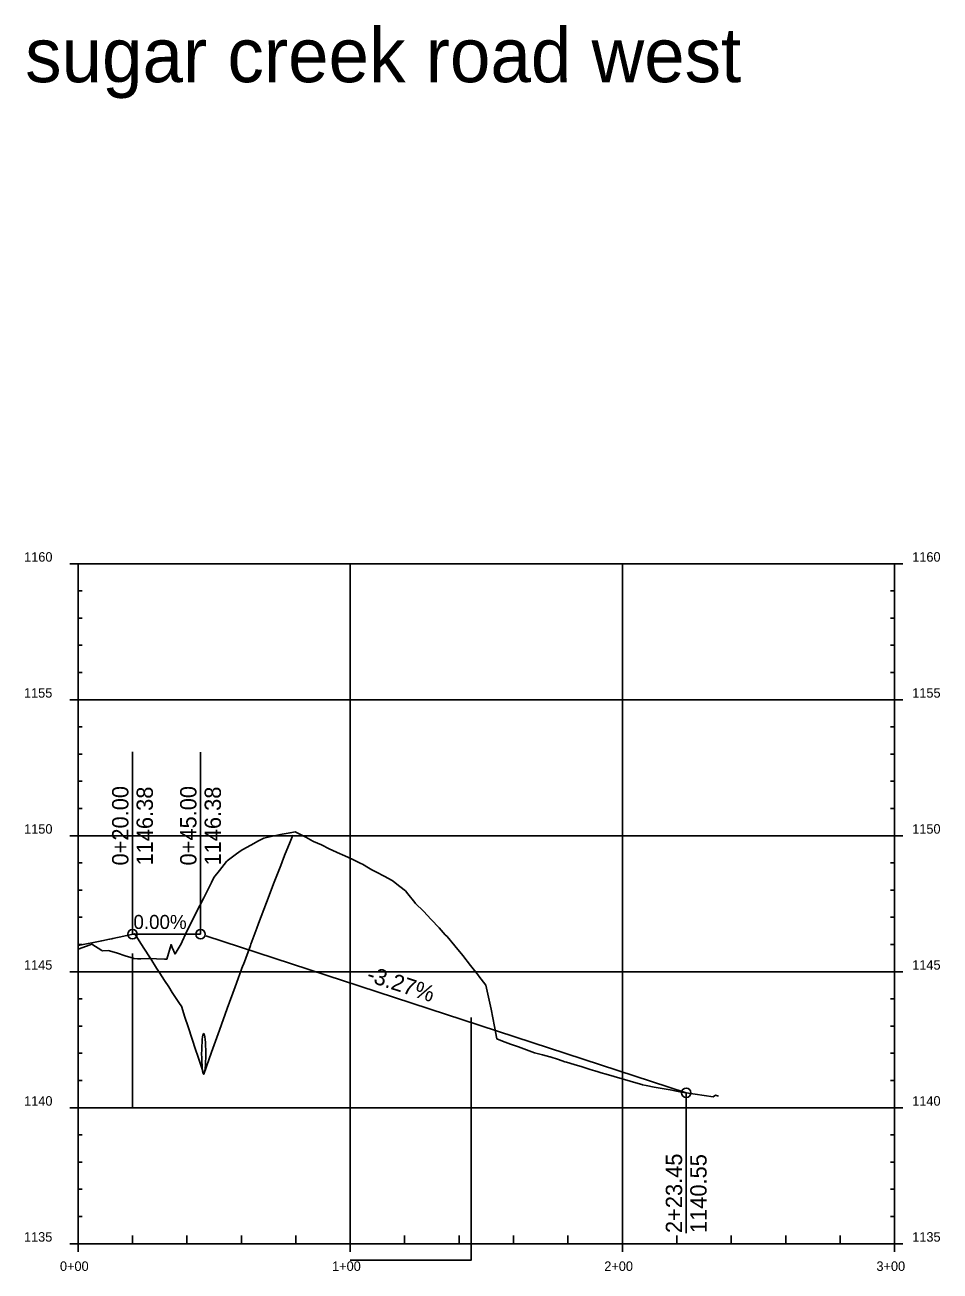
# Model space of a CAD drawing. Extents: x 688474 to 694748, y 765018 to 767373.
# Drawn here: x 694411.9 to 694748.1, y 765808.2 to 766266.3 of the extents above; entities that cross this region are included whole.
import ezdxf

# ---------------------------------------------------------------- set-up
doc = ezdxf.new("R2010")
doc.units = 0
for name, color, linetype in [('30', 7, 'Continuous'), ('37', 7, 'Continuous'), ('R_Drainage', 7, 'Continuous'), ('R_Exist Surface', 7, 'Continuous'), ('R_Fin Surface', 7, 'Continuous'), ('R_No Plot', 7, 'Continuous'), ('R_Vert Alg', 7, 'Continuous'), ('R_Vert Alg Annot', 7, 'Continuous')]:
    doc.layers.add(name, color=color, linetype=linetype)

msp = doc.modelspace()

# ---------------------------------------------------------------- linework, layer by layer
at = {"layer": '37'}
for p, q in [((694428.38, 766068.21), (694431.38, 766068.21)), ((694428.38, 766068.21), (694431.38, 766068.21)), ((694431.38, 765818.21), (694431.38, 766068.21)), ((694431.38, 766068.21), (694731.38, 766068.21)), ((694431.38, 766068.21), (694731.38, 766068.21)), ((694531.38, 765818.21), (694531.38, 766068.21)), ((694631.38, 765818.21), (694631.38, 766068.21)), ((694731.38, 765818.21), (694731.38, 766068.21)), ((694734.38, 766068.21), (694731.38, 766068.21)), ((694734.38, 766068.21), (694731.38, 766068.21)), ((694431.38, 766058.21), (694432.88, 766058.21)), ((694731.38, 766058.21), (694729.88, 766058.21)), ((694431.38, 766048.21), (694432.88, 766048.21)), ((694731.38, 766048.21), (694729.88, 766048.21)), ((694431.38, 766038.21), (694432.88, 766038.21)), ((694731.38, 766038.21), (694729.88, 766038.21)), ((694431.38, 766028.21), (694432.88, 766028.21)), ((694731.38, 766028.21), (694729.88, 766028.21)), ((694428.38, 766018.21), (694431.38, 766018.21)), ((694431.38, 766018.21), (694731.38, 766018.21)), ((694734.38, 766018.21), (694731.38, 766018.21)), ((694431.38, 766008.21), (694432.88, 766008.21)), ((694731.38, 766008.21), (694729.88, 766008.21)), ((694431.38, 765998.21), (694432.88, 765998.21)), ((694731.38, 765998.21), (694729.88, 765998.21)), ((694431.38, 765988.21), (694432.88, 765988.21)), ((694731.38, 765988.21), (694729.88, 765988.21)), ((694431.38, 765978.21), (694432.88, 765978.21)), ((694731.38, 765978.21), (694729.88, 765978.21)), ((694428.38, 765968.21), (694431.38, 765968.21)), ((694431.38, 765968.21), (694731.38, 765968.21)), ((694734.38, 765968.21), (694731.38, 765968.21)), ((694431.38, 765958.21), (694432.88, 765958.21)), ((694731.38, 765958.21), (694729.88, 765958.21)), ((694431.38, 765948.21), (694432.88, 765948.21)), ((694731.38, 765948.21), (694729.88, 765948.21)), ((694431.38, 765938.21), (694432.88, 765938.21)), ((694731.38, 765938.21), (694729.88, 765938.21)), ((694431.38, 765928.21), (694432.88, 765928.21)), ((694731.38, 765928.21), (694729.88, 765928.21)), ((694428.38, 765918.21), (694431.38, 765918.21)), ((694431.38, 765918.21), (694731.38, 765918.21)), ((694734.38, 765918.21), (694731.38, 765918.21)), ((694431.38, 765908.21), (694432.88, 765908.21)), ((694731.38, 765908.21), (694729.88, 765908.21)), ((694431.38, 765898.21), (694432.88, 765898.21)), ((694731.38, 765898.21), (694729.88, 765898.21)), ((694431.38, 765888.21), (694432.88, 765888.21)), ((694731.38, 765888.21), (694729.88, 765888.21)), ((694431.38, 765878.21), (694432.88, 765878.21)), ((694731.38, 765878.21), (694729.88, 765878.21)), ((694428.38, 765868.21), (694431.38, 765868.21)), ((694431.38, 765868.21), (694731.38, 765868.21)), ((694734.38, 765868.21), (694731.38, 765868.21)), ((694431.38, 765858.21), (694432.88, 765858.21)), ((694731.38, 765858.21), (694729.88, 765858.21)), ((694431.38, 765848.21), (694432.88, 765848.21)), ((694731.38, 765848.21), (694729.88, 765848.21)), ((694431.38, 765838.21), (694432.88, 765838.21)), ((694731.38, 765838.21), (694729.88, 765838.21)), ((694431.38, 765828.21), (694432.88, 765828.21)), ((694731.38, 765828.21), (694729.88, 765828.21)), ((694428.38, 765818.21), (694431.38, 765818.21)), ((694431.38, 765818.21), (694731.38, 765818.21)), ((694431.38, 765815.21), (694431.38, 765818.21)), ((694451.38, 765818.21), (694451.38, 765821.21)), ((694471.38, 765818.21), (694471.38, 765821.21)), ((694491.38, 765818.21), (694491.38, 765821.21)), ((694511.38, 765818.21), (694511.38, 765821.21)), ((694531.38, 765815.21), (694531.38, 765818.21)), ((694551.38, 765818.21), (694551.38, 765821.21)), ((694571.38, 765818.21), (694571.38, 765821.21)), ((694591.38, 765818.21), (694591.38, 765821.21)), ((694611.38, 765818.21), (694611.38, 765821.21)), ((694631.38, 765815.21), (694631.38, 765818.21)), ((694651.38, 765818.21), (694651.38, 765821.21)), ((694671.38, 765818.21), (694671.38, 765821.21)), ((694691.38, 765818.21), (694691.38, 765821.21)), ((694711.38, 765818.21), (694711.38, 765821.21)), ((694734.38, 765818.21), (694731.38, 765818.21)), ((694731.38, 765815.21), (694731.38, 765818.21))]:
    msp.add_line(p, q, dxfattribs=at)
at = {"layer": 'R_Drainage'}
msp.add_ellipse((694477.55, 765888.03), major_axis=(0, 7.5), ratio=0.1, dxfattribs=at)
at = {"layer": 'R_Exist Surface'}
msp.add_lwpolyline([(694431.38, 765926.45), (694435.79, 765928.13), (694436.41, 765928.39), (694440.06, 765925.99), (694440.1, 765925.96), (694440.31, 765925.81), (694440.49, 765925.84), (694442.41, 765926.06), (694442.94, 765925.89), (694445.83, 765925), (694448.71, 765924.1), (694451.59, 765923.21), (694451.92, 765923.11), (694453.19, 765922.95), (694454.48, 765922.98), (694457.26, 765923.05), (694457.36, 765923.05), (694460.24, 765922.96), (694463.13, 765922.89), (694464.05, 765922.86), (694465.58, 765928.19), (694466.01, 765927.16), (694467.06, 765924.72), (694467.07, 765924.73), (694468.9, 765927.82), (694468.98, 765927.96), (694471.57, 765933.61), (694471.78, 765934.04), (694474.66, 765939.75), (694477.55, 765945.43), (694480.43, 765951.07), (694481.33, 765952.81), (694483.32, 765955.41), (694485.87, 765958.72), (694486.2, 765958.98), (694489.08, 765961.2), (694490.91, 765962.59), (694491.97, 765963.18), (694494.85, 765964.77), (694497.74, 765966.33), (694499.63, 765967.32), (694500.62, 765967.55), (694503.5, 765968.18), (694506.39, 765968.76), (694509.27, 765969.31), (694511.21, 765969.65), (694512.16, 765969.18), (694515.04, 765967.67), (694517.62, 765966.24), (694517.92, 765966.12), (694520.81, 765964.82), (694523.69, 765963.45), (694526.32, 765962.14), (694526.58, 765962.03), (694529.46, 765960.77), (694532.34, 765959.44), (694535.23, 765958.04), (694535.88, 765957.7), (694538.11, 765956.42), (694539.35, 765955.68), (694541, 765954.84), (694543.88, 765953.3), (694546.76, 765951.69), (694547.28, 765951.39), (694549.65, 765949.54), (694551.65, 765947.91), (694552.53, 765946.85), (694555.12, 765943.63), (694555.42, 765943.35), (694558.3, 765940.46), (694561.18, 765937.46), (694564.07, 765934.35), (694566.33, 765931.82), (694566.95, 765931.11), (694569.83, 765927.69), (694572.72, 765924.16), (694575.6, 765920.52), (694576.59, 765919.24), (694578.49, 765916.81), (694578.63, 765916.63), (694581.2, 765913.24), (694581.42, 765912.21), (694583.13, 765904.4), (694584.36, 765898.02), (694585.27, 765893.48), (694587.3, 765892.72), (694590.23, 765891.63), (694590.63, 765891.48), (694593.17, 765890.54), (694596.1, 765889.46), (694599.04, 765888.38), (694599.08, 765888.37), (694601.98, 765887.64), (694604.76, 765886.94), (694604.91, 765886.89), (694607.85, 765885.92), (694610.19, 765885.14), (694610.79, 765884.96), (694613.72, 765884.07), (694616.66, 765883.19), (694619.6, 765882.3), (694621.21, 765881.82), (694622.53, 765881.39), (694623.58, 765881.06), (694625.47, 765880.5), (694628.4, 765879.64), (694631.34, 765878.78), (694634.28, 765877.92), (694637.21, 765877.07), (694638.53, 765876.69), (694638.72, 765876.62), (694638.75, 765876.61), (694640.15, 765876.33), (694643.09, 765875.76), (694646.02, 765875.23), (694648.96, 765874.73), (694651.29, 765874.36), (694651.89, 765874.22), (694653.08, 765873.94), (694654.83, 765873.67), (694664.75, 765872.23), (694665.58, 765872.84), (694666.7, 765872.52)], dxfattribs=at)
at = {"layer": 'R_Fin Surface'}
msp.add_lwpolyline([(694431.38, 765927.8), (694431.41, 765927.8), (694440.06, 765929.57), (694442.94, 765930.15), (694443.81, 765930.33), (694444.22, 765930.41), (694445.83, 765930.76), (694445.9, 765930.78), (694447.08, 765931.03), (694448.71, 765931.4), (694451.59, 765932.03), (694452.19, 765932.17), (694454.48, 765928.56), (694457.36, 765924.03), (694458.08, 765922.91), (694460.24, 765919.52), (694461.39, 765917.74), (694463.13, 765915.03), (694464.69, 765912.63), (694466.01, 765910.57), (694468.9, 765906.14), (694469.33, 765905.49), (694470.64, 765901.47), (694471.78, 765897.99), (694474.66, 765889.24), (694474.91, 765888.49), (694474.94, 765888.41), (694475, 765888.22), (694476.71, 765883.07), (694477.55, 765880.54), (694477.55, 765880.53), (694480.43, 765888.67), (694483.32, 765896.75), (694486.2, 765904.75), (694489.08, 765912.68), (694491.97, 765920.52), (694492.12, 765920.91), (694494.7, 765927.89), (694494.85, 765928.3), (694497.09, 765934.27), (694497.74, 765936), (694500.62, 765943.63), (694503.5, 765951.17), (694505.85, 765957.23), (694506.39, 765958.63), (694507.29, 765960.94), (694509.27, 765966.01), (694510.24, 765968.47)], dxfattribs=at)
at = {"layer": 'R_No Plot'}
msp.add_line((694451.38, 765868.21), (694451.38, 765924.93), dxfattribs=at)
msp.add_lwpolyline([(694531.38, 765812.21), (694575.83, 765812.21), (694575.83, 765901.33)], dxfattribs=at)
at = {"layer": 'R_Vert Alg'}
for p, q in [((694451.38, 765932.01), (694476.38, 765932.01)), ((694478.36, 765931.36), (694654.83, 765873.71))]:
    msp.add_line(p, q, dxfattribs=at)
for centre in [(694451.38, 765932.01), (694476.38, 765932.01), (694654.83, 765873.71)]:
    msp.add_circle(centre, 1.75, dxfattribs=at)
at = {"layer": 'R_Vert Alg Annot'}
for p, q in [((694451.38, 765932.01), (694451.38, 765999.03)), ((694476.38, 765932.01), (694476.38, 765998.93)), ((694654.83, 765873.71), (694654.83, 765822.14))]:
    msp.add_line(p, q, dxfattribs=at)

# ---------------------------------------------------------------- texts
at = {"layer": '30'}
for s, p in [('1160', (694411.57, 766068.96)), ('1160', (694411.57, 766068.96)), ('1160', (694737.88, 766068.96)), ('1160', (694737.88, 766068.96)), ('1155', (694411.51, 766018.96)), ('1155', (694737.88, 766018.96)), ('1150', (694411.57, 765968.96)), ('1150', (694737.88, 765968.96)), ('1145', (694411.51, 765918.96)), ('1145', (694737.88, 765918.96)), ('1140', (694411.57, 765868.96)), ('1140', (694737.88, 765868.96)), ('1135', (694411.51, 765818.96)), ('1135', (694737.88, 765818.96)), ('0+00', (694424.73, 765808.21)), ('1+00', (694524.73, 765808.21)), ('2+00', (694624.73, 765808.21)), ('3+00', (694724.73, 765808.21))]:
    msp.add_text(s, height=3.5, dxfattribs=at).set_placement(p)
at = {"layer": 'R_Vert Alg Annot'}
msp.add_text('sugar creek road west', height=20, dxfattribs=at).set_placement((694411.95, 766245.24))
for s, height, rotation, p in [('0+20.00', 6, 90, (694449.88, 765957.27)), ('1146.38', 6, 90, (694458.88, 765957.27)), ('0+45.00', 6, 90, (694474.88, 765957.27)), ('1146.38', 6, 90, (694483.88, 765957.27)), ('0.00%', 5.155, 360, (694451.73, 765933.93)), ('-3.27%', 6, 341.9077, (694537.04, 765914.86)), ('2+23.45', 6, 90, (694653.33, 765822.14)), ('1140.55', 6, 90, (694662.33, 765822.14))]:
    msp.add_text(s, height=height, rotation=rotation, dxfattribs=at).set_placement(p)

doc.saveas('drawing.dxf')
